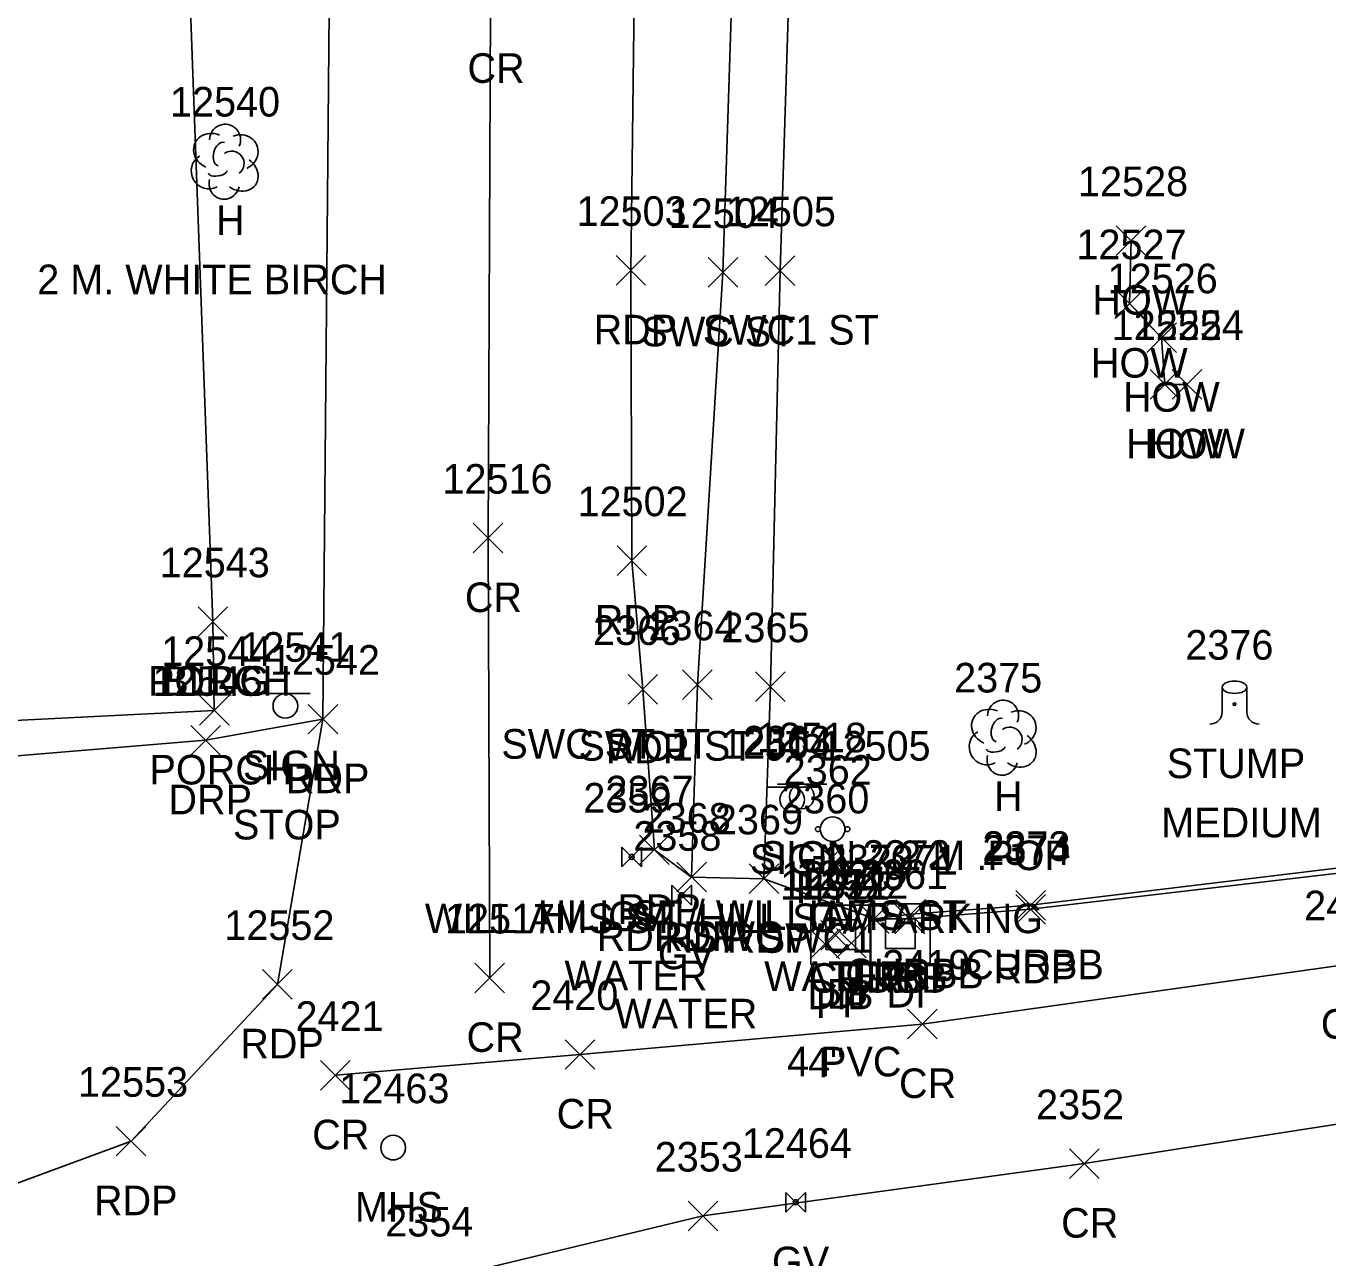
# Model space of a CAD drawing. Extents: x 1769141 to 1770817, y 735471 to 742405.
# Drawn here: x 1770233.5 to 1770321.5, y 741128 to 741211.2 of the extents above; entities that cross this region are included whole.
import ezdxf

# ---------------------------------------------------------------- set-up
doc = ezdxf.new("R2010")
doc.units = 0
for name, color, linetype in [('D_A', 7, 'Continuous'), ('D_C', 7, 'Continuous'), ('D_I', 7, 'Continuous'), ('D_TIC', 7, 'Continuous'), ('DS', 7, 'Continuous'), ('L_A', 7, 'Continuous'), ('L_C', 7, 'Continuous'), ('L_I', 7, 'Continuous'), ('L_TIC', 7, 'Continuous'), ('LBC', 7, 'Continuous'), ('LBF', 7, 'Continuous'), ('LTD', 7, 'Continuous'), ('LTS', 7, 'Continuous'), ('P_A', 7, 'Continuous'), ('P_I', 7, 'Continuous'), ('P_TIC', 7, 'Continuous'), ('PET', 7, 'Continuous'), ('PRC', 7, 'Continuous'), ('R_A', 7, 'Continuous'), ('R_I', 7, 'Continuous'), ('R_TIC', 7, 'Continuous'), ('RC', 7, 'Continuous'), ('RDP', 7, 'Continuous'), ('RSW', 7, 'Continuous'), ('S_A', 7, 'Continuous'), ('S_C', 7, 'Continuous'), ('S_I', 7, 'Continuous'), ('SSGN', 7, 'Continuous'), ('U_A', 7, 'Continuous'), ('U_C', 7, 'Continuous'), ('U_I', 7, 'Continuous'), ('USMH', 7, 'Continuous'), ('UWFH', 7, 'Continuous'), ('UWV', 7, 'Continuous')]:
    doc.layers.add(name, color=color, linetype=linetype)

msp = doc.modelspace()

# ---------------------------------------------------------------- linework, layer by layer
at = {"layer": 'D_TIC'}
for points in [[(1770287.215, 741148.832), (1770289.215, 741150.832)], [(1770289.215, 741148.832), (1770287.215, 741150.832)], [(1770288.272, 741148.296), (1770290.272, 741150.296)], [(1770290.272, 741148.296), (1770288.272, 741150.296)], [(1770286.485, 741148.242), (1770288.485, 741150.242)], [(1770288.485, 741148.242), (1770286.485, 741150.242)]]:
    msp.add_lwpolyline(points, dxfattribs=at)
at = {"layer": 'DS'}
for p, q in [((1770286.55, 741151.862), (1770290.55, 741151.862)), ((1770286.55, 741147.862), (1770286.55, 741151.862)), ((1770290.55, 741151.862), (1770290.55, 741147.862)), ((1770290.594, 741151.945), (1770294.594, 741151.945)), ((1770290.594, 741147.945), (1770290.594, 741151.945)), ((1770294.594, 741151.945), (1770294.594, 741147.945)), ((1770287.55, 741148.862), (1770287.55, 741150.862)), ((1770287.55, 741150.862), (1770289.55, 741150.862)), ((1770289.55, 741150.862), (1770289.55, 741148.862)), ((1770291.594, 741148.945), (1770291.594, 741150.945)), ((1770291.594, 741150.945), (1770293.594, 741150.945)), ((1770293.594, 741150.945), (1770293.594, 741148.945)), ((1770288.556, 741149.864), (1770288.556, 741149.864)), ((1770288.556, 741149.864), (1770288.556, 741149.864)), ((1770292.599, 741149.946), (1770292.599, 741149.946)), ((1770292.599, 741149.946), (1770292.599, 741149.946)), ((1770289.55, 741148.862), (1770287.55, 741148.862)), ((1770293.594, 741148.945), (1770291.594, 741148.945)), ((1770290.55, 741147.862), (1770286.55, 741147.862)), ((1770294.594, 741147.945), (1770290.594, 741147.945))]:
    msp.add_line(p, q, dxfattribs=at)
at = {"layer": 'L_TIC'}
for points in [[(1770307.178, 741195.749), (1770309.178, 741197.749)], [(1770309.178, 741195.749), (1770307.178, 741197.749)], [(1770307.073, 741191.491), (1770309.073, 741193.491)], [(1770309.073, 741191.491), (1770307.073, 741193.491)], [(1770309.237, 741189.19), (1770311.237, 741191.19)], [(1770311.237, 741189.19), (1770309.237, 741191.19)], [(1770309.454, 741186.032), (1770311.454, 741188.032)], [(1770311.454, 741186.032), (1770309.454, 741188.032)], [(1770310.945, 741186.038), (1770312.945, 741188.038)], [(1770312.945, 741186.038), (1770310.945, 741188.038)], [(1770245.143, 741170.006), (1770247.143, 741172.006)], [(1770247.143, 741170.006), (1770245.143, 741172.006)], [(1770245.143, 741170.006), (1770247.143, 741172.006)], [(1770247.143, 741170.006), (1770245.143, 741172.006)], [(1770245.245, 741164.014), (1770247.245, 741166.014)], [(1770247.245, 741164.014), (1770245.245, 741166.014)]]:
    msp.add_lwpolyline(points, dxfattribs=at)
at = {"layer": 'LBC'}
for points in [[(1770243.487, 741246.601), (1770244.451, 741217.306), (1770246.143, 741171.006)], [(1770311.945, 741187.038), (1770310.454, 741187.032), (1770310.237, 741190.19), (1770308.073, 741192.491), (1770308.178, 741196.749)]]:
    msp.add_lwpolyline(points, dxfattribs=at)
at = {"layer": 'LBF'}
msp.add_lwpolyline([(1770246.143, 741171.006), (1770246.245, 741165.014), (1770221.075, 741163.757), (1770221.204, 741153.68), (1770218.238, 741153.485)], dxfattribs=at)
at = {"layer": 'LTD'}
for p, q in [((1770246.929, 741202.129), (1770246.929, 741202.129)), ((1770246.929, 741202.129), (1770246.929, 741202.129)), ((1770299.482, 741163.227), (1770299.482, 741163.227)), ((1770299.482, 741163.227), (1770299.482, 741163.227))]:
    msp.add_line(p, q, dxfattribs=at)
for centre in [(1770246.976, 741203.563), (1770299.529, 741164.661)]:
    msp.add_arc(centre, 1.047, 335.52715, 180.95627, dxfattribs=at)
for centre, major_axis, ratio, start_param, end_param in [((1770246.137, 741202.796), (1.21, -0.512), 0.895232, 1.570796, 4.712389), ((1770247.971, 741202.713), (-1.141, -0.483), 0.949671, 1.570796, 4.712389), ((1770246.721, 741202.588), (-0.208, -0.792), 0.645439, 3.141593, 6.283185), ((1770245.846, 741201.421), (0.584, -1.042), 0.959034, 3.141593, 6.283185), ((1770247.429, 741201.963), (-0.5, 0.667), 0.989748, 3.141593, 6.283185), ((1770247.929, 741201.296), (-1.09, 0.792), 0.841452, 1.570796, 4.712389), ((1770246.471, 741201.379), (-0.625, -0.083), 0.423636, 0, 3.141593), ((1770246.929, 741200.629), (0.265, 1.061), 0.942809, 1.570796, 4.712389), ((1770298.691, 741163.894), (1.21, -0.512), 0.895232, 1.570796, 4.712389), ((1770299.274, 741163.686), (-0.208, -0.792), 0.645439, 3.141593, 6.283185), ((1770300.524, 741163.811), (-1.141, -0.483), 0.949671, 1.570796, 4.712389), ((1770298.399, 741162.519), (0.584, -1.042), 0.959034, 3.141593, 6.283185), ((1770299.982, 741163.061), (-0.5, 0.667), 0.989748, 3.141593, 6.283185), ((1770299.024, 741162.477), (-0.625, -0.083), 0.423636, 0, 3.141593), ((1770300.483, 741162.394), (-1.09, 0.792), 0.841452, 1.570796, 4.712389), ((1770299.483, 741161.727), (0.265, 1.061), 0.942809, 1.570796, 4.712389)]:
    msp.add_ellipse(centre, major_axis=major_axis, ratio=ratio, start_param=start_param, end_param=end_param, dxfattribs=at)
at = {"layer": 'LTS'}
for p, q in [((1770314.326, 741166.582), (1770314.326, 741164.915)), ((1770315.993, 741166.415), (1770315.993, 741166.582)), ((1770315.993, 741166.582), (1770315.993, 741164.915)), ((1770315.16, 741165.44), (1770315.16, 741165.44)), ((1770315.16, 741165.44), (1770315.16, 741165.44)), ((1770315.16, 741165.415), (1770315.16, 741165.415))]:
    msp.add_line(p, q, dxfattribs=at)
msp.add_circle((1770315.16, 741165.44), 0.0833, dxfattribs=at)
for centre, start, end in [((1770313.493, 741164.915), 270, 360), ((1770316.826, 741164.915), 180, 270)]:
    msp.add_arc(centre, 0.833, start, end, dxfattribs=at)
msp.add_ellipse((1770315.16, 741166.582), major_axis=(-0.833, 0), ratio=0.5, dxfattribs=at)
at = {"layer": 'P_TIC'}
for points in [[(1770273.38, 741193.741), (1770275.38, 741195.741)], [(1770275.38, 741193.741), (1770273.38, 741195.741)], [(1770263.734, 741175.655), (1770265.734, 741177.655)], [(1770265.734, 741175.655), (1770263.734, 741177.655)], [(1770273.449, 741174.134), (1770275.449, 741176.134)], [(1770275.449, 741174.134), (1770273.449, 741176.134)], [(1770274.19, 741165.437), (1770276.19, 741167.437)], [(1770276.19, 741165.437), (1770274.19, 741167.437)], [(1770252.586, 741163.425), (1770254.586, 741165.425)], [(1770254.586, 741163.425), (1770252.586, 741165.425)], [(1770274.977, 741154.599), (1770276.977, 741156.599)], [(1770276.977, 741154.599), (1770274.977, 741156.599)], [(1770277.489, 741152.762), (1770279.489, 741154.762)], [(1770279.489, 741152.762), (1770277.489, 741154.762)], [(1770282.376, 741152.643), (1770284.376, 741154.643)], [(1770284.376, 741152.643), (1770282.376, 741154.643)], [(1770300.387, 741150.584), (1770302.387, 741152.584)], [(1770302.387, 741150.584), (1770300.387, 741152.584)], [(1770289.834, 741149.945), (1770291.834, 741151.945)], [(1770291.834, 741149.945), (1770289.834, 741151.945)], [(1770292.216, 741149.928), (1770294.216, 741151.928)], [(1770294.216, 741149.928), (1770292.216, 741151.928)], [(1770263.851, 741145.949), (1770265.851, 741147.949)], [(1770265.851, 741145.949), (1770263.851, 741147.949)], [(1770249.51, 741145.509), (1770251.51, 741147.509)], [(1770251.51, 741145.509), (1770249.51, 741147.509)], [(1770293.064, 741142.832), (1770295.064, 741144.832)], [(1770295.064, 741142.832), (1770293.064, 741144.832)], [(1770269.938, 741140.774), (1770271.938, 741142.774)], [(1770271.938, 741140.774), (1770269.938, 741142.774)], [(1770253.424, 741139.369), (1770255.424, 741141.369)], [(1770255.424, 741139.369), (1770253.424, 741141.369)], [(1770239.624, 741134.92), (1770241.624, 741136.92)], [(1770241.624, 741134.92), (1770239.624, 741136.92)], [(1770304.015, 741133.401), (1770306.015, 741135.401)], [(1770306.015, 741133.401), (1770304.015, 741135.401)], [(1770278.252, 741129.869), (1770280.252, 741131.869)], [(1770280.252, 741129.869), (1770278.252, 741131.869)]]:
    msp.add_lwpolyline(points, dxfattribs=at)
at = {"layer": 'PET'}
for points in [[(1770255.757, 741305.939), (1770254.292, 741251.357), (1770254.048, 741217.356), (1770253.586, 741164.425), (1770250.51, 741146.509), (1770240.624, 741135.92), (1770219.618, 741128.165)], [(1770274.449, 741175.134), (1770274.38, 741194.741), (1770274.966, 741242.188)], [(1770275.19, 741166.437), (1770274.449, 741175.134)], [(1770275.19, 741166.437), (1770275.977, 741155.599), (1770278.489, 741153.762), (1770283.376, 741153.643), (1770290.834, 741150.945), (1770293.216, 741150.928), (1770301.387, 741151.584), (1770330.449, 741154.982), (1770332.291, 741155.308), (1770348.778, 741157.994), (1770362.422, 741159.793), (1770366.418, 741160.492), (1770374.133, 741161.731), (1770375.956, 741162.233), (1770400.806, 741165.909), (1770403.378, 741166.25), (1770419.604, 741168.76)]]:
    msp.add_lwpolyline(points, dxfattribs=at)
at = {"layer": 'PRC'}
for points in [[(1770265.56, 741284.713), (1770265.204, 741250.684), (1770264.911, 741212.404), (1770264.734, 741176.655), (1770264.851, 741146.949)], [(1770420.662, 741161.961), (1770386.961, 741157.659), (1770355.709, 741152.482), (1770322.559, 741147.84), (1770294.064, 741143.832), (1770270.938, 741141.774), (1770254.424, 741140.369)], [(1770422.288, 741154.401), (1770391.031, 741148.9), (1770351.212, 741141.744), (1770324.852, 741137.505), (1770305.015, 741134.401), (1770279.252, 741130.869), (1770261.05, 741126.482)]]:
    msp.add_lwpolyline(points, dxfattribs=at)
at = {"layer": 'R_TIC'}
for points in [[(1770279.604, 741193.604), (1770281.604, 741195.604)], [(1770281.604, 741193.604), (1770279.604, 741195.604)], [(1770283.465, 741193.72), (1770285.465, 741195.72)], [(1770285.465, 741193.72), (1770283.465, 741195.72)], [(1770277.878, 741165.753), (1770279.878, 741167.753)], [(1770279.878, 741165.753), (1770277.878, 741167.753)], [(1770282.808, 741165.622), (1770284.808, 741167.622)], [(1770284.808, 741165.622), (1770282.808, 741167.622)], [(1770252.586, 741163.425), (1770254.586, 741165.425)], [(1770254.586, 741163.425), (1770252.586, 741165.425)], [(1770244.656, 741162), (1770246.656, 741164)], [(1770246.656, 741162), (1770244.656, 741164)], [(1770277.489, 741152.762), (1770279.489, 741154.762)], [(1770279.489, 741152.762), (1770277.489, 741154.762)], [(1770282.376, 741152.643), (1770284.376, 741154.643)], [(1770284.376, 741152.643), (1770282.376, 741154.643)], [(1770292.288, 741150.247), (1770294.288, 741152.247)], [(1770294.288, 741150.247), (1770292.288, 741152.247)], [(1770300.388, 741150.851), (1770302.388, 741152.851)], [(1770302.388, 741150.851), (1770300.388, 741152.851)], [(1770289.834, 741149.945), (1770291.834, 741151.945)], [(1770291.834, 741149.945), (1770289.834, 741151.945)]]:
    msp.add_lwpolyline(points, dxfattribs=at)
at = {"layer": 'RC'}
msp.add_lwpolyline([(1770290.834, 741150.945), (1770293.288, 741151.247), (1770301.388, 741151.851), (1770330.25, 741155.349), (1770332.291, 741155.308)], dxfattribs=at)
at = {"layer": 'RDP'}
msp.add_lwpolyline([(1770253.586, 741164.425), (1770245.656, 741163), (1770229.113, 741161.629), (1770218.725, 741146.837), (1770219.798, 741130.241), (1770219.618, 741128.165)], dxfattribs=at)
at = {"layer": 'RSW'}
for points in [[(1770280.604, 741194.604), (1770282.073, 741240.289)], [(1770284.465, 741194.72), (1770285.882, 741239.846)], [(1770278.878, 741166.753), (1770280.604, 741194.604)], [(1770283.808, 741166.622), (1770284.465, 741194.72)], [(1770278.878, 741166.753), (1770278.489, 741153.762)], [(1770283.808, 741166.622), (1770283.376, 741153.643)]]:
    msp.add_lwpolyline(points, dxfattribs=at)
at = {"layer": 'SSGN'}
for p, q in [((1770249.395, 741166.154), (1770252.728, 741166.154)), ((1770251.042, 741165.321), (1770251.042, 741165.321)), ((1770284.289, 741160.038), (1770287.623, 741160.038)), ((1770283.631, 741159.824), (1770286.964, 741159.824)), ((1770285.936, 741159.205), (1770285.936, 741159.205)), ((1770285.277, 741158.991), (1770285.277, 741158.991))]:
    msp.add_line(p, q, dxfattribs=at)
for centre in [(1770251.042, 741165.321), (1770285.936, 741159.205), (1770285.277, 741158.991)]:
    msp.add_circle(centre, 0.833, dxfattribs=at)
at = {"layer": 'USMH'}
for p, q in [((1770258.326, 741135.485), (1770258.326, 741135.485)), ((1770259.159, 741135.485), (1770259.159, 741135.485))]:
    msp.add_line(p, q, dxfattribs=at)
msp.add_circle((1770258.326, 741135.485), 0.833, dxfattribs=at)
at = {"layer": 'UWFH'}
msp.add_line((1770288.013, 741156.995), (1770288.013, 741156.995), dxfattribs=at)
for centre, radius in [((1770288.013, 741156.995), 0.833), ((1770287.013, 741156.995), 0.167), ((1770289.013, 741156.995), 0.167), ((1770288.013, 741155.995), 0.167)]:
    msp.add_circle(centre, radius, dxfattribs=at)
at = {"layer": 'UWV'}
for p, q in [((1770273.774, 741155.786), (1770275.107, 741154.452)), ((1770275.107, 741155.786), (1770273.774, 741154.452)), ((1770287.269, 741155.724), (1770288.602, 741154.391)), ((1770288.602, 741155.724), (1770287.269, 741154.391)), ((1770277.145, 741153.202), (1770278.478, 741151.868)), ((1770278.478, 741153.202), (1770277.145, 741151.868)), ((1770284.849, 741132.461), (1770286.182, 741131.127)), ((1770286.182, 741132.461), (1770284.849, 741131.127))]:
    msp.add_line(p, q, dxfattribs=at)
for points in [[(1770273.774, 741155.786), (1770273.774, 741154.452)], [(1770275.107, 741154.452), (1770275.107, 741155.786)], [(1770287.269, 741155.724), (1770287.269, 741154.391)], [(1770288.602, 741154.391), (1770288.602, 741155.724)], [(1770277.145, 741153.202), (1770277.145, 741151.868)], [(1770278.478, 741151.868), (1770278.478, 741153.202)], [(1770284.849, 741132.461), (1770284.849, 741131.127)], [(1770286.182, 741131.127), (1770286.182, 741132.461)]]:
    msp.add_lwpolyline(points, dxfattribs=at)
for centre in [(1770274.441, 741155.119), (1770287.935, 741155.058), (1770277.811, 741152.535), (1770285.515, 741131.794)]:
    msp.add_circle(centre, 0.167, dxfattribs=at)

# ---------------------------------------------------------------- texts
at = {"layer": 'D_A'}
for s, p in [('DIB', (1770286.318, 741144.832)), ('DI', (1770287.611, 741144.864)), ('DI', (1770291.655, 741144.946)), ('P', (1770286.863, 741144.242)), ('P', (1770288.65, 741144.296))]:
    msp.add_text(s, height=2, dxfattribs=at).set_placement(p)
at = {"layer": 'D_C'}
for s, p in [('4 PVC', (1770284.933, 741140.296)), ('4"', (1770286.351, 741140.242))]:
    msp.add_text(s, height=2, dxfattribs=at).set_placement(p)
at = {"layer": 'D_I'}
for s, p in [('12520', (1770284.538, 741152.832)), ('12519', (1770285.524, 741152.864)), ('2361', (1770289.859, 741152.946)), ('12521', (1770284.462, 741152.242)), ('12522', (1770285.681, 741152.296))]:
    msp.add_text(s, height=2, dxfattribs=at).set_placement(p)
at = {"layer": 'L_A'}
for s, p in [('H', (1770246.362, 741197.129)), ('HOW', (1770305.564, 741191.749)), ('HOW', (1770305.459, 741187.491)), ('HOW', (1770307.623, 741185.19)), ('HOW', (1770307.84, 741182.032)), ('HOW', (1770309.331, 741182.038)), ('PORCH', (1770241.765, 741166.006)), ('BLDG', (1770242.734, 741166.006)), ('PORCH', (1770241.867, 741160.014)), ('STUMP', (1770310.58, 741160.442)), ('H', (1770298.916, 741158.227))]:
    msp.add_text(s, height=2, dxfattribs=at).set_placement(p)
at = {"layer": 'L_C'}
for s, p in [('2 M. WHITE BIRCH', (1770234.284, 741193.129)), ('MEDIUM', (1770310.21, 741156.442)), ('2 M .POP', (1770292.514, 741154.227))]:
    msp.add_text(s, height=2, dxfattribs=at).set_placement(p)
at = {"layer": 'L_I'}
for s, p in [('12540', (1770243.252, 741205.129)), ('12528', (1770304.588, 741199.749)), ('12527', (1770304.482, 741195.491)), ('12526', (1770306.591, 741193.19)), ('12525', (1770306.863, 741190.032)), ('12524', (1770308.355, 741190.038)), ('12543', (1770242.553, 741174.006)), ('12543', (1770242.553, 741174.006)), ('12544', (1770242.654, 741168.014)), ('2376', (1770311.84, 741168.442)), ('2375', (1770296.223, 741166.227))]:
    msp.add_text(s, height=2, dxfattribs=at).set_placement(p)
at = {"layer": 'P_A'}
for s, p in [('CR', (1770263.344, 741207.404)), ('RDP', (1770271.868, 741189.741)), ('CR', (1770263.167, 741171.655)), ('RDP', (1770271.937, 741170.134)), ('RDP', (1770272.678, 741161.437)), ('RDP', (1770251.074, 741159.425)), ('RDP', (1770273.466, 741150.599)), ('RDP', (1770275.977, 741148.762)), ('RDP', (1770280.864, 741148.643)), ('RDP', (1770298.875, 741146.584)), ('RDP', (1770288.322, 741145.945)), ('RDP', (1770290.704, 741145.928)), ('CR', (1770320.992, 741142.84)), ('RDP', (1770247.998, 741141.509)), ('CR', (1770263.284, 741141.949)), ('CR', (1770292.497, 741138.832)), ('CR', (1770269.371, 741136.774)), ('CR', (1770252.857, 741135.369)), ('RDP', (1770238.112, 741130.92)), ('CR', (1770303.449, 741129.401))]:
    msp.add_text(s, height=2, dxfattribs=at).set_placement(p)
at = {"layer": 'P_I'}
for s, p in [('12503', (1770270.711, 741197.741)), ('12516', (1770261.656, 741179.655)), ('12502', (1770270.78, 741178.134)), ('2366', (1770271.828, 741169.437)), ('12542', (1770249.995, 741167.425)), ('2367', (1770272.67, 741158.599)), ('2368', (1770275.182, 741156.762)), ('2369', (1770280.061, 741156.643)), ('2374', (1770298.127, 741154.584)), ('2370', (1770287.488, 741153.945)), ('2371', (1770290.523, 741153.928)), ('2418', (1770319.866, 741150.84)), ('12552', (1770246.92, 741149.509)), ('12517', (1770261.827, 741149.949)), ('2419', (1770291.363, 741146.832)), ('2420', (1770267.591, 741144.774)), ('2421', (1770251.731, 741143.369)), ('12553', (1770237.034, 741138.92)), ('2352', (1770301.756, 741137.401)), ('2353', (1770275.992, 741133.869)), ('2354', (1770257.79, 741129.482))]:
    msp.add_text(s, height=2, dxfattribs=at).set_placement(p)
at = {"layer": 'R_A'}
for s, p in [('SWC ST', (1770275.101, 741189.604)), ('SWC1 ST', (1770279.245, 741189.72)), ('SWC ST JT 12504', (1770265.635, 741161.753)), ('SWC1 ST JT 12505', (1770270.848, 741161.622)), ('DRP', (1770251.074, 741159.425)), ('DRP', (1770243.144, 741158)), ('RDP SWC', (1770272.071, 741148.762)), ('RDP SWC1', (1770276.636, 741148.643)), ('CURBB', (1770296.971, 741146.851)), ('CURBB', (1770286.417, 741145.945)), ('CURBB', (1770288.871, 741146.247))]:
    msp.add_text(s, height=2, dxfattribs=at).set_placement(p)
at = {"layer": 'R_I'}
for s, p in [('12504', (1770276.935, 741197.604)), ('12505', (1770280.796, 741197.72)), ('2364', (1770275.571, 741169.753)), ('2365', (1770280.501, 741169.622)), ('12542', (1770249.995, 741167.425)), ('12545', (1770242.066, 741166)), ('2368', (1770275.182, 741156.762)), ('2369', (1770280.061, 741156.643)), ('2373', (1770298.129, 741154.851)), ('2370', (1770287.488, 741153.945)), ('2372', (1770290.028, 741154.247))]:
    msp.add_text(s, height=2, dxfattribs=at).set_placement(p)
at = {"layer": 'S_A'}
for p in [(1770248.18, 741160.301), (1770282.415, 741153.971), (1770283.074, 741154.185)]:
    msp.add_text('SIGN', height=2, dxfattribs=at).set_placement(p)
at = {"layer": 'S_C'}
for s, p in [('STOP', (1770247.503, 741156.301)), ('WILLIAMS ST /HILL ST/ PARKING', (1770260.464, 741149.971)), ('HILL ST / WILLIAMS ST', (1770268.083, 741150.185))]:
    msp.add_text(s, height=2, dxfattribs=at).set_placement(p)
at = {"layer": 'S_I'}
for s, p in [('12541', (1770247.999, 741168.301)), ('2363', (1770281.951, 741161.971)), ('12518', (1770282.893, 741162.185))]:
    msp.add_text(s, height=2, dxfattribs=at).set_placement(p)
at = {"layer": 'U_A'}
for s, p in [('HYD', (1770285.533, 741151.995)), ('GV', (1770272.842, 741150.119)), ('GV', (1770286.337, 741150.058)), ('GV', (1770276.213, 741147.535)), ('MHS', (1770255.743, 741130.485)), ('GV', (1770283.917, 741126.794))]:
    msp.add_text(s, height=2, dxfattribs=at).set_placement(p)
at = {"layer": 'U_C'}
for p in [(1770269.898, 741146.119), (1770283.392, 741146.058), (1770273.268, 741143.535)]:
    msp.add_text('WATER', height=2, dxfattribs=at).set_placement(p)
at = {"layer": 'U_I'}
for s, p in [('2362', (1770284.706, 741159.995)), ('2359', (1770271.173, 741158.119)), ('2360', (1770284.542, 741158.058)), ('2358', (1770274.552, 741155.535)), ('12463', (1770254.688, 741138.485)), ('12464', (1770281.878, 741134.794))]:
    msp.add_text(s, height=2, dxfattribs=at).set_placement(p)

doc.saveas('drawing.dxf')
